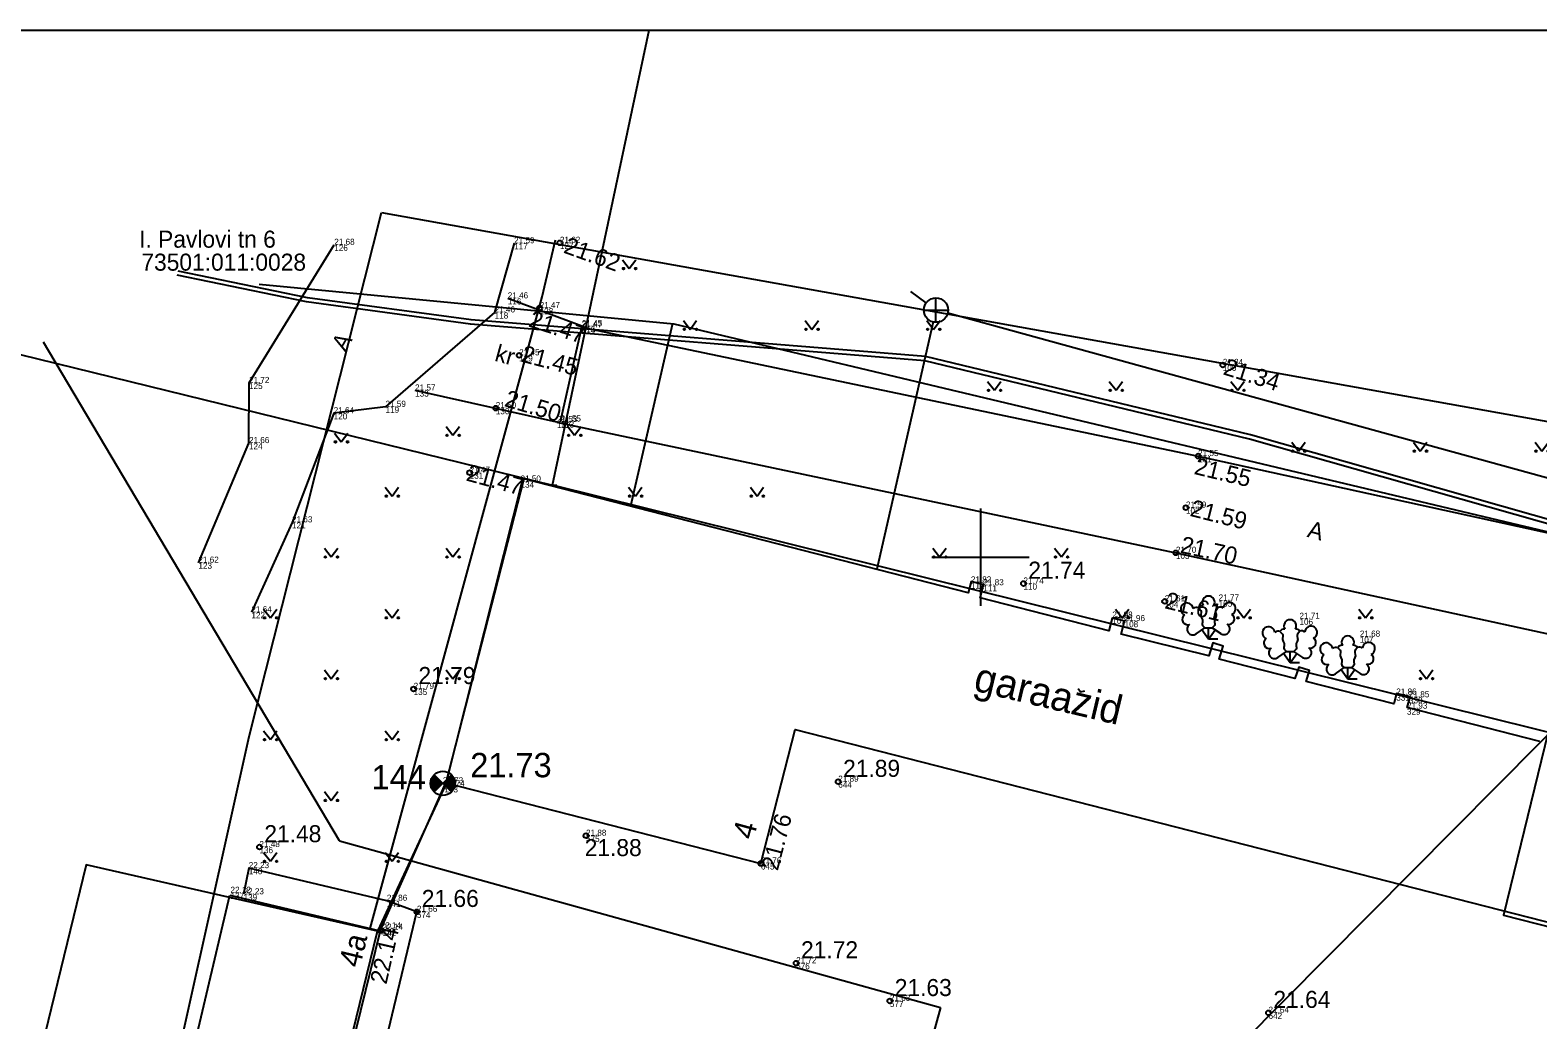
# Model space of a CAD drawing. Extents: x 714279 to 714471, y 6589851 to 6590083.
# Drawn here: x 714310.9 to 714372.9, y 6590031 to 6590071.6 of the extents above; entities that cross this region are included whole.
import ezdxf

# ---------------------------------------------------------------- set-up
doc = ezdxf.new("R2010")
doc.units = 0
for name, color, linetype in [('AED', 7, 'Continuous'), ('ALUSVORK', 7, 'Continuous'), ('HALJASTUS', 7, 'Continuous'), ('HOONE', 7, 'Continuous'), ('KKAEV', 7, 'Continuous'), ('KORGUS', 7, 'Continuous'), ('KTRASS', 7, 'Continuous'), ('MOOTKORG', 7, 'Continuous'), ('MOOTMPUNKT', 7, 'Continuous'), ('MOOTPIIR', 7, 'Continuous'), ('MPKAABEL', 7, 'Continuous'), ('PIIR', 7, 'Continuous'), ('PUU', 7, 'Continuous'), ('SITRASS', 7, 'Continuous'), ('SKTRASS', 7, 'Continuous'), ('TEE', 7, 'Continuous'), ('TTRASS', 7, 'Continuous'), ('VORK', 7, 'Continuous'), ('VORMISTUS', 7, 'Continuous')]:
    doc.layers.add(name, color=color, linetype=linetype)

# ---------------------------------------------------------------- blocks, each defined once
blk = doc.blocks.new('RING02')
at = {"layer": 'KORGUS'}
blk.add_circle((0, 0), 0.2, dxfattribs=at)
blk = doc.blocks.new('RING02_2')
at = {"layer": 'KORGUS'}
blk.add_circle((0, 0), 0.2, dxfattribs=at)
blk = doc.blocks.new('RING02_1')
at = {"layer": 'KORGUS'}
blk.add_circle((0, 0), 0.2, dxfattribs=at)
blk = doc.blocks.new('LEHTP3')
at = {"layer": 'PUU'}
for p, q in [((-1.02, 0.44), (-0.3, 0.95)), ((0, 0), (-0.55, 0.77)), ((-0.3, 0.95), (0.29, 0.95)), ((0, 0), (0, 0.95)), ((0, 0), (0.54, 0.78)), ((0.76, 0), (0, 0)), ((0.29, 0.95), (1.01, 0.46))]:
    blk.add_line(p, q, dxfattribs=at)
for points in [[(-0.83, 2.57), (-0.62, 2.37), (-0.59, 2.31), (-0.59, 2.2), (-0.62, 2.02), (-0.62, 1.93), (-0.58, 1.77), (-0.5, 1.59), (-0.48, 1.5), (-0.49, 1.41), (-0.52, 1.28), (-0.52, 1.22), (-0.48, 1.14), (-0.43, 1.08), (-0.3, 0.95)], [(0.81, 2.6), (0.62, 2.37), (0.59, 2.31), (0.59, 2.2), (0.62, 2.02), (0.63, 1.93), (0.59, 1.77), (0.51, 1.59), (0.49, 1.5), (0.5, 1.41), (0.53, 1.28), (0.53, 1.22), (0.49, 1.14), (0.44, 1.08), (0.3, 0.95)]]:
    blk.add_lwpolyline(points, dxfattribs=at)
for centre, radius, start, end in [((-1.77, 2.47), 0.512, 125.5389, 246.5536), ((-1.77, 2.47), 0.512, 4.5218, 125.5364), ((-0.99, 2.21), 0.403, 65.2382, 130.7412), ((-0.48, 2.38), 0.403, 84.7965, 150.2995), ((0, 3.04), 0.512, 90.0013, 211.0159), ((0, 3.04), 0.512, 328.9841, 89.9987), ((0.48, 2.38), 0.403, 34.3857, 95.2035), ((0.95, 2.23), 0.403, 50.3173, 111.1351), ((1.72, 2.51), 0.512, 55.522, 176.5367), ((1.72, 2.51), 0.512, 294.5049, 55.5195), ((-1.71, 1.64), 0.448, 125.4667, 288.5349), ((1.28, 0.85), 0.475, 235.5219, 55.5208), ((1.68, 1.67), 0.448, 252.5235, 55.5918), ((-1.29, 0.83), 0.475, 125.5377, 305.5366)]:
    blk.add_arc(centre, radius, start, end, dxfattribs=at)
blk = doc.blocks.new('POINT_DISPLAY')
blk.add_line((0, 0), (0, 0))
blk = doc.blocks.new('REEPER')
at = {"layer": 'ALUSVORK'}
for p, q in [((-0.71, 0.71), (0.71, -0.71)), ((-0.71, -0.71), (0.71, 0.71))]:
    blk.add_line(p, q, dxfattribs=at)
blk.add_circle((0, 0), 1, dxfattribs=at)
for radius, start, end in [(0.95, 135.0005, 224.9995), (0.9, 135.0005, 224.9995), (0.85, 135.0005, 224.9995), (0.8, 135.0005, 224.9995), (0.75, 135.0005, 224.9995), (0.7, 135.0005, 224.9995), (0.65, 135.0005, 224.9995), (0.6, 135.0005, 224.9995), (0.55, 135.0005, 224.9995), (0.5, 135.0005, 224.9995), (0.45, 135.0005, 224.9995), (0.4, 135.0005, 224.9995), (0.35, 135.0005, 224.9995), (0.3, 135.0005, 224.9995), (0.25, 135.0005, 224.9995), (0.2, 135.0005, 224.9995), (0.15, 135.0005, 224.9995), (0.1, 135.0005, 224.9995), (0.05, 135.0005, 224.9995), (0.05, 315.0005, 44.9995), (0.1, 315.0005, 44.9995), (0.15, 315.0005, 44.9995), (0.2, 315.0005, 44.9995), (0.25, 315.0005, 44.9995), (0.3, 315.0005, 44.9995), (0.35, 315.0005, 44.9995), (0.4, 315.0005, 44.9995), (0.45, 315.0005, 44.9995), (0.5, 315.0005, 44.9995), (0.55, 315.0005, 44.9995), (0.6, 315.0005, 44.9995), (0.65, 315.0005, 44.9995), (0.7, 315.0005, 44.9995), (0.75, 315.0005, 44.9995), (0.8, 315.0005, 44.9995), (0.85, 315.0005, 44.9995), (0.9, 315.0005, 44.9995), (0.95, 315.0005, 44.9995)]:
    blk.add_arc((0, 0), radius, start, end, dxfattribs=at)
for p in [(-0.71, 0.71), (-0.71, 0.71), (0.71, 0.71), (-0.71, -0.71), (0.71, -0.71), (0.71, -0.71)]:
    blk.add_blockref('POINT_DISPLAY', p, dxfattribs=at)
blk = doc.blocks.new('KAKAEV')
at = {"layer": 'KKAEV'}
for p, q in [((-1, 0), (1, 0)), ((0, -1), (0, 1))]:
    blk.add_line(p, q, dxfattribs=at)
blk.add_circle((0, 0), 1, dxfattribs=at)
blk = doc.blocks.new('MURU_1')
at = {"layer": 'HALJASTUS'}
for p, q in [((-0.93, 1.21), (0, 0)), ((0, 0), (0.89, 1.21))]:
    blk.add_line(p, q, dxfattribs=at)
for centre in [(-0.8, 0), (0.86, 0)]:
    blk.add_circle(centre, 0.11, dxfattribs=at)

msp = doc.modelspace()

# ---------------------------------------------------------------- linework, layer by layer
at = {"layer": 'AED'}
msp.add_lwpolyline([(714325.33, 6590034.654), (714328.034, 6590040.733)], dxfattribs=at)
at = {"layer": 'HOONE'}
for points in [[(714331.232, 6590053.217), (714328.034, 6590040.733), (714340.977, 6590037.417), (714342.388, 6590042.923), (714381.181, 6590032.985)], [(714372.976, 6590042.431), (714367.537, 6590043.824), (714367.648, 6590044.261), (714367.095, 6590044.403), (714366.983, 6590043.966), (714363.381, 6590044.889), (714363.518, 6590045.348), (714363.075, 6590045.478), (714362.919, 6590045.016), (714359.805, 6590045.81), (714359.976, 6590046.347), (714359.543, 6590046.473), (714359.374, 6590045.941), (714355.783, 6590046.835), (714355.919, 6590047.364), (714355.41, 6590047.494), (714355.275, 6590046.966), (714349.984, 6590048.321), (714350.124, 6590048.866), (714349.615, 6590048.997), (714349.497, 6590048.538), (714331.232, 6590053.217)], [(714354.006, 6590044.601), (714354.114, 6590044.469), (714354.28, 6590044.51)], [(714319.159, 6590036.112), (714325.33, 6590034.654), (714314.842, 6589991.992), (714309.058, 6589993.359), (714319.159, 6590036.112)]]:
    msp.add_lwpolyline(points, dxfattribs=at)
at = {"layer": 'KORGUS'}
for centre in [(714344.153, 6590040.773), (714340.977, 6590037.417), (714325.33, 6590034.654), (714361.834, 6590031.282)]:
    msp.add_circle(centre, 0.1, dxfattribs=at)
at = {"layer": 'KTRASS'}
for points in [[(714347.768, 6590060.445), (714347.132, 6590060.907)], [(714388.535, 6590049.05), (714348.653, 6590060.023)], [(714348.049, 6590059.658), (714345.744, 6590049.499)]]:
    msp.add_lwpolyline(points, dxfattribs=at)
at = {"layer": 'MOOTPIIR'}
msp.add_lwpolyline([(714325.392, 6590064.148), (714418.405, 6590047.495), (714428.059, 6590039.059), (714392.952, 6589961.13), (714372.822, 6589966.903), (714302.696, 6589965.199), (714319.941, 6590042.637), (714325.392, 6590064.148)], dxfattribs=at)
at = {"layer": 'MPKAABEL'}
for points in [[(714324.913, 6590034.743), (714331.987, 6590060.695), (714332.53, 6590063.025)], [(714372.768, 6590021.51), (714371.67, 6590021.813), (714372.903, 6590026.299), (714377.515, 6590025.926), (714382.377, 6590024.932), (714383.808, 6590025.49), (714388.238, 6590038.714), (714390.005, 6590045.675), (714389.318, 6590046.817), (714361.052, 6590054.85), (714347.71, 6590058.063), (714329.047, 6590059.566), (714322.309, 6590060.484), (714316.991, 6590061.578)], [(714372.812, 6590021.678), (714371.882, 6590021.934), (714373.032, 6590026.115), (714377.491, 6590025.755), (714382.392, 6590024.752), (714383.947, 6590025.358), (714388.404, 6590038.665), (714390.19, 6590045.703), (714389.431, 6590046.965), (714361.096, 6590055.017), (714347.738, 6590058.234), (714329.065, 6590059.739), (714322.338, 6590060.654), (714317.026, 6590061.747)]]:
    msp.add_lwpolyline(points, dxfattribs=at)
at = {"layer": 'PIIR'}
for points in [[(714309.195, 6590064.025), (714308.241, 6590058.889), (714332.408, 6590052.951), (714336.379, 6590071.638)], [(714331.191, 6590053.239), (714328.01, 6590040.642), (714325.217, 6590034.631), (714313.247, 6590037.362), (714302.809, 6589994.583), (714314.816, 6589992.023), (714325.215, 6590034.631)], [(714313.433, 6589985.9), (714378.228, 6589973.152), (714405.629, 6590034.791), (714332.408, 6590052.951), (714332.595, 6590052.951)], [(714373.326, 6590042.802), (714371.485, 6590035.288), (714381.325, 6590032.79), (714383.187, 6590040.304)]]:
    msp.add_lwpolyline(points, dxfattribs=at)
at = {"layer": 'SITRASS'}
for points in [[(714320.359, 6590061.207), (714337.402, 6590059.587), (714379.185, 6590049.636), (714371.595, 6590022.212), (714372.86, 6590021.865)], [(714337.342, 6590059.592), (714335.62, 6590052.093)]]:
    msp.add_lwpolyline(points, dxfattribs=at)
at = {"layer": 'SKTRASS'}
msp.add_lwpolyline([(714355.498, 6590024.768), (714385.19, 6590054.667)], dxfattribs=at)
at = {"layer": 'TEE'}
for points in [[(714317.862, 6590049.77), (714319.94, 6590054.682), (714319.942, 6590057.151), (714323.445, 6590062.827)], [(714330.837, 6590062.888), (714330.035, 6590060.049), (714325.551, 6590056.173), (714323.421, 6590055.907), (714321.708, 6590051.427), (714320.04, 6590047.732)], [(714333.617, 6590059.482), (714330.575, 6590060.625)], [(714332.743, 6590055.569), (714333.617, 6590059.437)], [(714333.617, 6590059.437), (714358.94, 6590054.148), (714385.625, 6590048.292), (714406.584, 6590043.775), (714409.241, 6590043.211)], [(714332.593, 6590055.546), (714326.767, 6590056.843)], [(714332.593, 6590055.546), (714358.028, 6590050.175), (714384.824, 6590044.337), (714405.232, 6590039.925)], [(714308.915, 6589992.579), (714312.567, 6589991.748), (714315.741, 6589991.273), (714319.939, 6590006.608), (714326.841, 6590035.429), (714325.606, 6590035.884), (714319.931, 6590037.223), (714319.717, 6590036.149)]]:
    msp.add_lwpolyline(points, dxfattribs=at)
at = {"layer": 'TTRASS'}
for points in [[(714323.659, 6590038.348), (714311.499, 6590058.821)], [(714323.659, 6590038.348), (714348.356, 6590031.494)], [(714348.353, 6590031.495), (714346.654, 6590025.325)]]:
    msp.add_lwpolyline(points, dxfattribs=at)
at = {"layer": 'VORK'}
for p, q in [((714350, 6590052), (714350, 6590048)), ((714348, 6590050), (714352, 6590050))]:
    msp.add_line(p, q, dxfattribs=at)
at = {"layer": 'VORMISTUS'}
msp.add_lwpolyline([(714471.122, 6589929.143), (714278.622, 6589929.143), (714278.622, 6590071.643), (714471.122, 6590071.643), (714471.122, 6589929.143)], dxfattribs=at)

# ---------------------------------------------------------------- block references
at = {"layer": 'ALUSVORK', "xscale": 0.5, "yscale": 0.5}
msp.add_blockref('REEPER', (714327.904, 6590040.706), dxfattribs=at)
at = {"layer": 'HALJASTUS', "xscale": 0.3, "yscale": 0.3}
for p in [(714335.568, 6590061.852), (714338.068, 6590059.352), (714343.068, 6590059.352), (714348.068, 6590059.352), (714350.568, 6590056.852), (714355.568, 6590056.852), (714360.568, 6590056.852), (714328.32, 6590055.004), (714333.32, 6590055.004), (714323.733, 6590054.732), (714363.068, 6590054.352), (714368.068, 6590054.352), (714373.068, 6590054.352), (714325.82, 6590052.504), (714335.82, 6590052.504), (714340.82, 6590052.504), (714323.32, 6590050.004), (714328.32, 6590050.004), (714348.32, 6590050.004), (714353.32, 6590050.004), (714320.82, 6590047.504), (714325.82, 6590047.504), (714355.82, 6590047.504), (714360.82, 6590047.504), (714365.82, 6590047.504), (714323.32, 6590045.004), (714328.32, 6590045.004), (714368.32, 6590045.004), (714320.82, 6590042.504), (714325.82, 6590042.504), (714323.32, 6590040.004), (714320.82, 6590037.504), (714325.82, 6590037.504)]:
    msp.add_blockref('MURU_1', p, dxfattribs=at)
at = {"layer": 'KKAEV', "xscale": 0.5, "yscale": 0.5}
msp.add_blockref('KAKAEV', (714348.168, 6590060.144), dxfattribs=at)
at = {"layer": 'KORGUS', "xscale": 0.5, "yscale": 0.5}
for name, p in [('RING02', (714332.716, 6590062.908)), ('RING02_2', (714331.884, 6590060.227)), ('RING02_1', (714331.042, 6590058.286)), ('RING02', (714359.955, 6590057.892)), ('RING02_2', (714330.082, 6590056.117)), ('RING02_2', (714358.94, 6590054.148)), ('RING02', (714329.008, 6590053.469)), ('RING02_1', (714358.44, 6590052.031)), ('RING02_2', (714358.028, 6590050.175)), ('RING02', (714351.764, 6590048.912)), ('RING02', (714357.569, 6590048.179)), ('RING02', (714326.705, 6590044.585)), ('RING02', (714333.789, 6590038.554)), ('RING02', (714320.371, 6590038.088)), ('RING02_2', (714326.841, 6590035.429)), ('RING02', (714342.425, 6590033.32)), ('RING02', (714346.276, 6590031.769))]:
    msp.add_blockref(name, p, dxfattribs=at)
at = {"layer": 'PUU', "xscale": 0.5, "yscale": 0.5}
for p in [(714359.366, 6590046.625), (714362.72, 6590045.651), (714365.09, 6590044.985)]:
    msp.add_blockref('LEHTP3', p, dxfattribs=at)

# ---------------------------------------------------------------- texts
at = {"layer": 'ALUSVORK'}
for s, p in [('21.73', (714329.031, 6590040.956)), ('144', (714324.977, 6590040.456))]:
    msp.add_text(s, height=1, dxfattribs=at).set_placement(p)
at = {"layer": 'HOONE'}
for s, height, rotation, p in [('garaazid', 1.2, 346.63964, (714349.666, 6590044.521)), ('4', 0.9, 74.67241, (714340.665, 6590038.354)), ('4a', 0.9, 76.26888, (714324.496, 6590033.101))]:
    msp.add_text(s, height=height, rotation=rotation, dxfattribs=at).set_placement(p)
at = {"layer": 'KORGUS'}
for s, rotation, p in [('21.62', 340.10769, (714332.828, 6590062.512)), ('21.47', 342.13726, (714331.392, 6590059.478)), ('21.45', 345.30256, (714331.082, 6590058.035)), ('21.34', 342.53441, (714359.93, 6590057.513)), ('21.50', 343.45907, (714330.396, 6590056.208)), ('21.47', 344.65554, (714328.826, 6590053.152)), ('21.55', 346.42447, (714358.74, 6590053.418)), ('21.59', 345.75121, (714358.571, 6590051.697)), ('21.70', 347.79433, (714358.173, 6590050.184)), ('21.61', 346.47624, (714357.533, 6590047.903)), ('21.76', 75.38458, (714341.666, 6590037.086)), ('22.14', 77.18043, (714325.588, 6590032.424))]:
    msp.add_text(s, height=0.7, rotation=rotation, dxfattribs=at).set_placement(p)
for s, p in [('21.74', (714351.964, 6590049.112)), ('21.79', (714326.905, 6590044.785)), ('21.89', (714344.353, 6590040.973)), ('21.48', (714320.571, 6590038.288)), ('21.88', (714333.735, 6590037.717)), ('21.66', (714327.041, 6590035.629)), ('21.72', (714342.625, 6590033.52)), ('21.63', (714346.476, 6590031.969)), ('21.64', (714362.034, 6590031.482))]:
    msp.add_text(s, height=0.7, dxfattribs=at).set_placement(p)
at = {"layer": 'MOOTKORG'}
for s, p in [('21.68', (714323.445, 6590062.827)), ('21.59', (714330.837, 6590062.888)), ('21.62', (714332.716, 6590062.908)), ('21.46', (714330.035, 6590060.049)), ('21.46', (714330.575, 6590060.625)), ('21.47', (714331.884, 6590060.227)), ('21.45', (714333.617, 6590059.482)), ('21.47', (714333.617, 6590059.437)), ('21.45', (714331.042, 6590058.286)), ('21.34', (714359.955, 6590057.892)), ('21.72', (714319.942, 6590057.151)), ('21.57', (714326.767, 6590056.843)), ('21.64', (714323.421, 6590055.907)), ('21.59', (714325.551, 6590056.173)), ('21.50', (714330.082, 6590056.117)), ('21.53', (714332.593, 6590055.546)), ('21.55', (714332.743, 6590055.569)), ('21.66', (714319.94, 6590054.682)), ('21.55', (714358.94, 6590054.148)), ('21.47', (714329.008, 6590053.469)), ('21.50', (714331.099, 6590053.101)), ('21.59', (714358.44, 6590052.031)), ('21.63', (714321.708, 6590051.427)), ('21.70', (714358.028, 6590050.175)), ('21.62', (714317.862, 6590049.77)), ('21.82', (714349.605, 6590048.958)), ('21.74', (714351.764, 6590048.912)), ('21.83', (714350.117, 6590048.841)), ('21.64', (714320.04, 6590047.732)), ('21.61', (714357.569, 6590048.179)), ('21.77', (714359.784, 6590048.215)), ('21.98', (714355.415, 6590047.513)), ('21.96', (714355.92, 6590047.37)), ('21.71', (714363.106, 6590047.466)), ('21.68', (714365.584, 6590046.731)), ('21.79', (714326.705, 6590044.585)), ('21.86', (714367.082, 6590044.352)), ('21.85', (714367.605, 6590044.242)), ('21.93', (714367.524, 6590043.775)), ('21.73', (714327.904, 6590040.706)), ('21.74', (714327.969, 6590040.583)), ('21.89', (714344.153, 6590040.773)), ('21.88', (714333.789, 6590038.554)), ('21.48', (714320.371, 6590038.088)), ('22.23', (714319.931, 6590037.223)), ('21.76', (714340.977, 6590037.417)), ('22.12', (714319.182, 6590036.209)), ('22.23', (714319.717, 6590036.149)), ('21.86', (714325.606, 6590035.884)), ('21.66', (714326.841, 6590035.429)), ('22.14', (714325.353, 6590034.751)), ('22.14', (714325.427, 6590034.69)), ('21.72', (714342.425, 6590033.32)), ('21.63', (714346.276, 6590031.769)), ('21.64', (714361.834, 6590031.282))]:
    msp.add_text(s, height=0.25, dxfattribs=at).set_placement(p)
at = {"layer": 'MOOTMPUNKT'}
for s, p in [('126', (714323.445, 6590062.577)), ('117', (714330.837, 6590062.638)), ('127', (714332.716, 6590062.658)), ('116', (714330.575, 6590060.375)), ('118', (714330.035, 6590059.799)), ('128', (714331.884, 6590059.977)), ('115', (714333.617, 6590059.232)), ('114', (714333.617, 6590059.187)), ('129', (714331.042, 6590058.036)), ('100', (714359.955, 6590057.642)), ('125', (714319.942, 6590056.901)), ('133', (714326.767, 6590056.593)), ('119', (714325.551, 6590055.923)), ('130', (714330.082, 6590055.867)), ('120', (714323.421, 6590055.657)), ('132', (714332.593, 6590055.296)), ('113', (714332.743, 6590055.319)), ('124', (714319.94, 6590054.432)), ('101', (714358.94, 6590053.898)), ('131', (714329.008, 6590053.219)), ('134', (714331.099, 6590052.851)), ('102', (714358.44, 6590051.781)), ('121', (714321.708, 6590051.177)), ('123', (714317.862, 6590049.52)), ('103', (714358.028, 6590049.925)), ('112', (714349.605, 6590048.708)), ('111', (714350.117, 6590048.591)), ('110', (714351.764, 6590048.662)), ('104', (714357.569, 6590047.929)), ('105', (714359.784, 6590047.965)), ('122', (714320.04, 6590047.482)), ('109', (714355.415, 6590047.263)), ('108', (714355.92, 6590047.12)), ('106', (714363.106, 6590047.216)), ('107', (714365.584, 6590046.481)), ('135', (714326.705, 6590044.335)), ('331', (714367.082, 6590044.102)), ('330', (714367.605, 6590043.992)), ('329', (714367.524, 6590043.525)), ('144', (714327.904, 6590040.456)), ('143', (714327.969, 6590040.333)), ('644', (714344.153, 6590040.523)), ('136', (714320.371, 6590037.838)), ('575', (714333.789, 6590038.304)), ('645', (714340.977, 6590037.167)), ('140', (714319.931, 6590036.973)), ('137', (714319.182, 6590035.959)), ('139', (714319.717, 6590035.899)), ('141', (714325.606, 6590035.634)), ('574', (714326.841, 6590035.179)), ('138', (714325.353, 6590034.501)), ('142', (714325.427, 6590034.44)), ('576', (714342.425, 6590033.07)), ('577', (714346.276, 6590031.519)), ('642', (714361.834, 6590031.032))]:
    msp.add_text(s, height=0.25, dxfattribs=at).set_placement(p)
at = {"layer": 'PIIR'}
for s, p in [('I. Pavlovi tn 6', (714315.425, 6590062.709)), ('73501:011:0028', (714315.518, 6590061.764))]:
    msp.add_text(s, height=0.7, dxfattribs=at).set_placement(p)
at = {"layer": 'TEE'}
for s, rotation, p in [('A', 59.88941, (714323.897, 6590058.402)), ('kr', 344.61804, (714329.998, 6590058.07)), ('A', 344.73921, (714363.388, 6590050.837))]:
    msp.add_text(s, height=0.7, rotation=rotation, dxfattribs=at).set_placement(p)

doc.saveas('drawing.dxf')
